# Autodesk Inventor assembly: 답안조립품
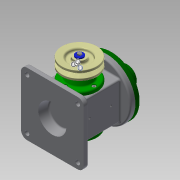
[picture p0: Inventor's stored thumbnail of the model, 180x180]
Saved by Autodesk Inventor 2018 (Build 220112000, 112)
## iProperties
Created: 2021-05
Part Number: 답안조립품
Material: 일반
Document SubType Name: Assembly
Designer: home
Author: home
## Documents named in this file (19)
- C:\Users\home\Desktop\710506V1014\답안조립품.iam
- C:\Users\home\Desktop\710506V1014\본체.ipt
- C:\Users\home\Desktop\710506V1014\뒤커버.ipt
- C:\Users\home\Desktop\710506V1014\베어링 17 x 40 x 12.ipt
- C:\Users\home\Desktop\710506V1014\편심축.ipt
- C:\Users\home\Desktop\710506V1014\앞커버.ipt
- C:\Users\home\Desktop\710506V1014\오일 실 17 30 8.ipt
- C:\Users\home\Desktop\710506V1014\키 4 x 4 x 12.ipt
- C:\Users\home\Desktop\710506V1014\V-벨트풀리.ipt
- C:\Users\home\Desktop\710506V1014\와셔 4x16.ipt
- C:\Users\home\Desktop\710506V1014\볼트 M4 x 10.ipt
- C:\Users\home\Desktop\710506V1014\볼트 M4 x 12.ipt
- 볼트 M4 x 12.ipt
- C:\Users\home\Desktop\710506V1014\링크.ipt
- C:\Users\home\Desktop\710506V1014\클레비스 핀 6 x 22.ipt
- 클레비스 핀 6 x 22.ipt
- C:\Users\home\Desktop\710506V1014\E-링.ipt
- C:\Users\home\Desktop\710506V1014\슬라이더.ipt
- C:\Users\home\Desktop\710506V1014\덮개.ipt
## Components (2 placed, 2 different names)
1. V-벨트풀리:1
2. E-링:1
